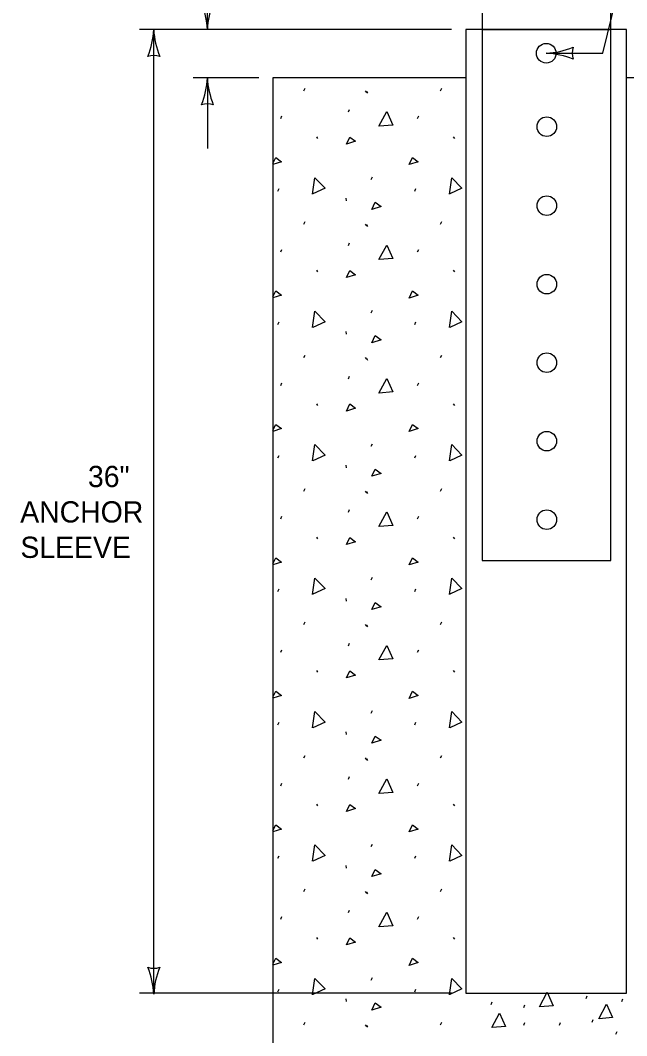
# Model space of a CAD drawing. Extents: x 49940 to 50043, y 49986 to 50011.
# Drawn here: x 49962.832 to 49964.546, y 49992.591 to 49995.459 of the extents above; entities that cross this region are included whole.
import ezdxf

# ---------------------------------------------------------------- set-up
doc = ezdxf.new("R2010")
doc.units = 0
for name, color, linetype in [('Level 1', 7, 'Continuous'), ('Level 2', 7, 'Continuous'), ('Level 3', 7, 'Continuous'), ('Level 4', 7, 'Continuous')]:
    doc.layers.add(name, color=color, linetype=linetype)

msp = doc.modelspace()

# ---------------------------------------------------------------- linework, layer by layer
at = {"layer": 'Level 1'}
for p, q in [((49964.5454, 49995.433), (49964.091, 49995.433)), ((49964.091, 49995.433), (49964.091, 49992.7114)), ((49964.5454, 49992.7114), (49964.5454, 49995.433)), ((49964.091, 49995.2967), (49963.5456, 49995.2967)), ((49963.5456, 49995.2967), (49963.5456, 49992.5705)), ((49965.0906, 49995.2967), (49964.5454, 49995.2967)), ((49963.6334, 49995.2603), (49963.6366, 49995.2675)), ((49963.8069, 49995.2603), (49963.8102, 49995.2553)), ((49963.8102, 49995.2584), (49963.8135, 49995.2536)), ((49964.0199, 49995.2603), (49964.0232, 49995.2675)), ((49963.568, 49995.1818), (49963.5711, 49995.1891)), ((49963.7592, 49995.2004), (49963.7624, 49995.2077)), ((49963.9546, 49995.1818), (49963.9578, 49995.1891)), ((49963.6688, 49995.1303), (49963.6721, 49995.1254)), ((49964.0554, 49995.1303), (49964.0586, 49995.1254)), ((49963.8238, 49995.0099), (49963.8271, 49995.0173)), ((49963.56, 49994.9768), (49963.5632, 49994.9842)), ((49963.9465, 49994.9768), (49963.9496, 49994.9842)), ((49963.7518, 49994.9566), (49963.7526, 49994.9492)), ((49963.6334, 49994.8833), (49963.6366, 49994.8906)), ((49963.8069, 49994.8833), (49963.8102, 49994.8784)), ((49963.8102, 49994.8813), (49963.8135, 49994.8766)), ((49964.0199, 49994.8833), (49964.0232, 49994.8906)), ((49963.7592, 49994.8235), (49963.7624, 49994.8308)), ((49963.568, 49994.805), (49963.5711, 49994.8122)), ((49963.9546, 49994.805), (49963.9578, 49994.8122)), ((49963.6688, 49994.7533), (49963.6721, 49994.7484)), ((49964.0554, 49994.7533), (49964.0586, 49994.7484)), ((49963.8238, 49994.633), (49963.8271, 49994.6403)), ((49963.56, 49994.5999), (49963.5632, 49994.6071)), ((49963.9465, 49994.5999), (49963.9496, 49994.6071)), ((49963.7518, 49994.5797), (49963.7526, 49994.5724)), ((49963.6334, 49994.5063), (49963.6366, 49994.5135)), ((49963.8069, 49994.5063), (49963.8102, 49994.5016)), ((49963.8102, 49994.5045), (49963.8135, 49994.4996)), ((49964.0199, 49994.5063), (49964.0232, 49994.5135)), ((49963.7592, 49994.4465), (49963.7624, 49994.4538)), ((49963.568, 49994.428), (49963.5711, 49994.4352)), ((49963.9546, 49994.428), (49963.9578, 49994.4352)), ((49963.6688, 49994.3763), (49963.6721, 49994.3713)), ((49964.0554, 49994.3763), (49964.0586, 49994.3713)), ((49963.8238, 49994.2561), (49963.8271, 49994.2633)), ((49963.56, 49994.2229), (49963.5632, 49994.2302)), ((49963.9465, 49994.2229), (49963.9496, 49994.2302)), ((49963.7518, 49994.2026), (49963.7526, 49994.1955)), ((49963.6334, 49994.1294), (49963.6366, 49994.1366)), ((49963.8069, 49994.1294), (49963.8102, 49994.1246)), ((49964.0199, 49994.1294), (49964.0232, 49994.1366)), ((49963.8102, 49994.1275), (49963.8135, 49994.1227)), ((49963.7592, 49994.0695), (49963.7624, 49994.0769)), ((49963.568, 49994.051), (49963.5711, 49994.0582)), ((49963.9546, 49994.051), (49963.9578, 49994.0582)), ((49963.6688, 49993.9994), (49963.6721, 49993.9944)), ((49964.0554, 49993.9994), (49964.0586, 49993.9944)), ((49963.8238, 49993.879), (49963.8271, 49993.8863)), ((49963.56, 49993.846), (49963.5632, 49993.8532)), ((49963.9465, 49993.846), (49963.9496, 49993.8532)), ((49963.7518, 49993.8256), (49963.7526, 49993.8185)), ((49963.6334, 49993.7523), (49963.6366, 49993.7596)), ((49964.0199, 49993.7523), (49964.0232, 49993.7596)), ((49963.8069, 49993.7523), (49963.8102, 49993.7475)), ((49963.8102, 49993.7505), (49963.8135, 49993.7457)), ((49963.7592, 49993.6926), (49963.7624, 49993.6999)), ((49963.568, 49993.674), (49963.5711, 49993.6813)), ((49963.9546, 49993.674), (49963.9578, 49993.6813)), ((49963.6688, 49993.6223), (49963.6721, 49993.6174)), ((49964.0554, 49993.6223), (49964.0586, 49993.6174)), ((49963.8238, 49993.5021), (49963.8271, 49993.5093)), ((49963.56, 49993.4691), (49963.5632, 49993.4763)), ((49963.9465, 49993.4691), (49963.9496, 49993.4763)), ((49963.7518, 49993.4489), (49963.7526, 49993.4415)), ((49963.6334, 49993.3754), (49963.6366, 49993.3827)), ((49964.0199, 49993.3754), (49964.0232, 49993.3827)), ((49963.8069, 49993.3754), (49963.8102, 49993.3706)), ((49963.8102, 49993.3735), (49963.8135, 49993.3687)), ((49963.568, 49993.297), (49963.5711, 49993.3042)), ((49963.7592, 49993.3156), (49963.7624, 49993.3229)), ((49963.9546, 49993.297), (49963.9578, 49993.3042)), ((49963.6688, 49993.2454), (49963.6721, 49993.2406)), ((49964.0554, 49993.2454), (49964.0586, 49993.2406)), ((49963.8238, 49993.1252), (49963.8271, 49993.1324)), ((49963.56, 49993.092), (49963.5632, 49993.0992)), ((49963.9465, 49993.092), (49963.9496, 49993.0992)), ((49963.7518, 49993.0717), (49963.7526, 49993.0645)), ((49963.6334, 49992.9984), (49963.6366, 49993.0057)), ((49963.8069, 49992.9984), (49963.8102, 49992.9936)), ((49963.8102, 49992.9966), (49963.8135, 49992.9917)), ((49964.0199, 49992.9984), (49964.0232, 49993.0057)), ((49963.568, 49992.92), (49963.5711, 49992.9274)), ((49963.7592, 49992.9385), (49963.7624, 49992.946)), ((49963.9546, 49992.92), (49963.9578, 49992.9274)), ((49963.6688, 49992.8684), (49963.6721, 49992.8636)), ((49964.0554, 49992.8684), (49964.0586, 49992.8636)), ((49963.8238, 49992.7481), (49963.8271, 49992.7553)), ((49963.56, 49992.7151), (49963.5632, 49992.7224)), ((49963.9465, 49992.7151), (49963.9496, 49992.7224)), ((49963.7518, 49992.6948), (49963.7526, 49992.6875)), ((49964.091, 49992.7114), (49964.5454, 49992.7114)), ((49964.4311, 49992.6959), (49964.4344, 49992.7032)), ((49964.5319, 49992.6876), (49964.5351, 49992.6949)), ((49964.1623, 49992.6793), (49964.1656, 49992.6865)), ((49964.2548, 49992.671), (49964.258, 49992.6782)), ((49964.4479, 49992.6289), (49964.4511, 49992.6364)), ((49963.6334, 49992.6214), (49963.6366, 49992.6287)), ((49963.8069, 49992.6214), (49963.8102, 49992.6166)), ((49963.8102, 49992.6197), (49963.8135, 49992.6148)), ((49964.0199, 49992.6214), (49964.0232, 49992.6287)), ((49964.2548, 49992.6206), (49964.258, 49992.628)), ((49964.3556, 49992.6206), (49964.3587, 49992.628)), ((49964.515, 49992.5957), (49964.5184, 49992.6029))]:
    msp.add_line(p, q, dxfattribs=at)
for points in [[(49964.137, 49996.3178), (49964.137, 49995.4332), (49964.5004, 49995.4332), (49964.5002, 49996.3179)], [(49963.8456, 49995.1601), (49963.8674, 49995.2012), (49963.8843, 49995.1633), (49963.8464, 49995.1601)], [(49963.7536, 49995.1093), (49963.7634, 49995.1294), (49963.7796, 49995.1174), (49963.7536, 49995.1093)], [(49963.5456, 49995.0551), (49963.5537, 49995.0717), (49963.5698, 49995.0597), (49963.5456, 49995.052)], [(49963.9307, 49995.0515), (49963.9403, 49995.0717), (49963.9563, 49995.0597), (49963.9307, 49995.0515)], [(49963.658, 49994.9684), (49963.6645, 49995.0146), (49963.6934, 49994.9849), (49963.659, 49994.9689)], [(49964.0447, 49994.9684), (49964.0512, 49995.0146), (49964.0801, 49994.9849), (49964.0455, 49994.9689)], [(49963.8254, 49994.9251), (49963.8352, 49994.9455), (49963.8514, 49994.9333), (49963.8254, 49994.9251)], [(49963.8456, 49994.7831), (49963.8674, 49994.8242), (49963.8843, 49994.7863), (49963.8464, 49994.7831)], [(49963.7536, 49994.7323), (49963.7634, 49994.7523), (49963.7796, 49994.7404), (49963.7536, 49994.7323)], [(49963.5456, 49994.6781), (49963.5537, 49994.6948), (49963.5698, 49994.6827), (49963.5456, 49994.6751)], [(49963.9307, 49994.6747), (49963.9403, 49994.6948), (49963.9563, 49994.6827), (49963.9307, 49994.6747)], [(49963.658, 49994.5916), (49963.6645, 49994.6377), (49963.6934, 49994.6079), (49963.659, 49994.5919)], [(49964.0447, 49994.5916), (49964.0512, 49994.6377), (49964.0801, 49994.6079), (49964.0455, 49994.5919)], [(49963.8254, 49994.5483), (49963.8352, 49994.5684), (49963.8514, 49994.5564), (49963.8254, 49994.5483)], [(49963.8456, 49994.4061), (49963.8674, 49994.4473), (49963.8843, 49994.4094), (49963.8464, 49994.4061)], [(49963.7536, 49994.3552), (49963.7634, 49994.3755), (49963.7796, 49994.3634), (49963.7536, 49994.3552)], [(49963.5456, 49994.301), (49963.5537, 49994.3178), (49963.5698, 49994.3057), (49963.5456, 49994.298)], [(49963.9307, 49994.2975), (49963.9403, 49994.3178), (49963.9563, 49994.3057), (49963.9307, 49994.2975)], [(49963.658, 49994.2147), (49963.6645, 49994.2607), (49963.6934, 49994.2309), (49963.659, 49994.2148)], [(49964.0447, 49994.2147), (49964.0512, 49994.2607), (49964.0801, 49994.2309), (49964.0455, 49994.2148)], [(49963.8254, 49994.1713), (49963.8352, 49994.1914), (49963.8514, 49994.1795), (49963.8254, 49994.1713)], [(49963.8456, 49994.0293), (49963.8674, 49994.0703), (49963.8843, 49994.0325), (49963.8464, 49994.0293)], [(49963.7536, 49993.9783), (49963.7634, 49993.9986), (49963.7796, 49993.9863), (49963.7536, 49993.9783)], [(49963.5456, 49993.9241), (49963.5537, 49993.9408), (49963.5698, 49993.9287), (49963.5456, 49993.9213)], [(49963.9307, 49993.9206), (49963.9403, 49993.9408), (49963.9563, 49993.9287), (49963.9307, 49993.9206)], [(49963.658, 49993.8376), (49963.6645, 49993.8838), (49963.6934, 49993.854), (49963.659, 49993.8379)], [(49964.0447, 49993.8376), (49964.0512, 49993.8838), (49964.0801, 49993.854), (49964.0455, 49993.8379)], [(49963.8254, 49993.7944), (49963.8352, 49993.8145), (49963.8514, 49993.8024), (49963.8254, 49993.7944)], [(49963.8456, 49993.6523), (49963.8674, 49993.6933), (49963.8843, 49993.6555), (49963.8464, 49993.6523)], [(49963.7536, 49993.6014), (49963.7634, 49993.6216), (49963.7796, 49993.6094), (49963.7536, 49993.6014)], [(49963.5456, 49993.5471), (49963.5537, 49993.5639), (49963.5698, 49993.5518), (49963.5456, 49993.5443)], [(49963.9307, 49993.5437), (49963.9403, 49993.5639), (49963.9563, 49993.5518), (49963.9307, 49993.5437)], [(49963.658, 49993.4607), (49963.6645, 49993.5069), (49963.6934, 49993.4769), (49963.659, 49993.461)], [(49964.0447, 49993.4607), (49964.0512, 49993.5069), (49964.0801, 49993.4769), (49964.0455, 49993.461)], [(49963.8254, 49993.4173), (49963.8352, 49993.4375), (49963.8514, 49993.4254), (49963.8254, 49993.4173)], [(49963.8456, 49993.2751), (49963.8674, 49993.3164), (49963.8843, 49993.2784), (49963.8464, 49993.2751)], [(49963.7536, 49993.2244), (49963.7634, 49993.2445), (49963.7796, 49993.2325), (49963.7536, 49993.2244)], [(49963.5456, 49993.1702), (49963.5537, 49993.1869), (49963.5698, 49993.1747), (49963.5456, 49993.1671)], [(49963.9307, 49993.1667), (49963.9403, 49993.1869), (49963.9563, 49993.1747), (49963.9307, 49993.1667)], [(49963.658, 49993.0836), (49963.6645, 49993.1297), (49963.6934, 49993.0999), (49963.659, 49993.084)], [(49964.0447, 49993.0836), (49964.0512, 49993.1297), (49964.0801, 49993.0999), (49964.0455, 49993.084)], [(49963.8254, 49993.0404), (49963.8352, 49993.0606), (49963.8514, 49993.0485), (49963.8254, 49993.0404)], [(49963.8456, 49992.8983), (49963.8674, 49992.9395), (49963.8843, 49992.9016), (49963.8464, 49992.8983)], [(49963.7536, 49992.8475), (49963.7634, 49992.8675), (49963.7796, 49992.8555), (49963.7536, 49992.8475)], [(49963.5456, 49992.7931), (49963.5537, 49992.8099), (49963.5698, 49992.7979), (49963.5456, 49992.7903)], [(49963.9307, 49992.7897), (49963.9403, 49992.8099), (49963.9563, 49992.7979), (49963.9307, 49992.7897)], [(49963.658, 49992.7066), (49963.6645, 49992.7529), (49963.6934, 49992.723), (49963.659, 49992.7072)], [(49964.0447, 49992.7066), (49964.0512, 49992.7529), (49964.0801, 49992.723), (49964.0455, 49992.7072)], [(49964.2992, 49992.6723), (49964.3208, 49992.7135), (49964.3378, 49992.6756), (49964.2999, 49992.6723)], [(49963.8254, 49992.6635), (49963.8352, 49992.6835), (49963.8514, 49992.6714), (49963.8254, 49992.6635)], [(49964.4671, 49992.6389), (49964.4888, 49992.6801), (49964.5058, 49992.6422), (49964.4679, 49992.6389)], [(49964.1647, 49992.6137), (49964.1865, 49992.6549), (49964.2035, 49992.617), (49964.1655, 49992.6137)]]:
    msp.add_lwpolyline(points, dxfattribs=at)
for centre in [(49964.3183, 49995.3662), (49964.3199, 49995.1587), (49964.3199, 49994.9356), (49964.3199, 49994.7138), (49964.3199, 49994.4921), (49964.3199, 49994.2704), (49964.3199, 49994.0487)]:
    msp.add_circle(centre, 0.0277, dxfattribs=at)
at = {"layer": 'Level 3'}
for p, q in [((49964.4785, 49995.3662), (49964.7583, 49996.5098)), ((49963.3606, 49995.433), (49963.3606, 49995.633)), ((49964.051, 49995.433), (49963.1691, 49995.433)), ((49963.2091, 49992.7081), (49963.2091, 49995.433)), ((49964.3183, 49995.3662), (49964.4785, 49995.3662)), ((49963.5056, 49995.2967), (49963.3206, 49995.2967)), ((49963.3606, 49995.2967), (49963.3606, 49995.0967)), ((49964.051, 49992.7114), (49963.1691, 49992.7114))]:
    msp.add_line(p, q, dxfattribs=at)
for centre, radius, start, end in [((49963.1279, 49995.4215), 0.233, 2.8273, 22.0772), ((49963.5828, 49995.4239), 0.2223, 157.456, 177.6395), ((49962.987, 49995.4422), 0.2223, 337.456, 357.6395), ((49963.4418, 49995.4445), 0.233, 182.8273, 202.0772), ((49964.3068, 49995.5989), 0.233, 272.8273, 292.0772), ((49964.3092, 49995.1441), 0.2223, 67.456, 87.6395), ((49964.4465, 49995.3662), 0.0548, 162.1388, 197.8612), ((49963.2091, 49995.3048), 0.0548, 72.1388, 107.8612), ((49963.1385, 49995.3059), 0.2223, 337.456, 357.6395), ((49963.5933, 49995.3082), 0.233, 182.8273, 202.0772), ((49963.3606, 49995.1685), 0.0548, 72.1388, 107.8612), ((49963.2091, 49992.8363), 0.0548, 252.1388, 287.8612), ((49962.9764, 49992.6966), 0.233, 2.8273, 22.0772), ((49963.4313, 49992.699), 0.2223, 157.456, 177.6395)]:
    msp.add_arc(centre, radius, start, end, dxfattribs=at)
at = {"layer": 'Level 4'}
for p, q in [((49964.137, 49995.4332), (49964.137, 49993.9336)), ((49964.5004, 49993.9336), (49964.5004, 49995.4332)), ((49964.137, 49993.9336), (49964.5004, 49993.9336))]:
    msp.add_line(p, q, dxfattribs=at)

# ---------------------------------------------------------------- texts
at = {"layer": 'Level 2'}
for s, p in [('36"', (49963.0231, 49994.1406)), ('ANCHOR', (49962.8318, 49994.0406)), ('SLEEVE', (49962.8323, 49993.9406))]:
    msp.add_text(s, height=0.06, dxfattribs=at).set_placement(p)

doc.saveas('drawing.dxf')
